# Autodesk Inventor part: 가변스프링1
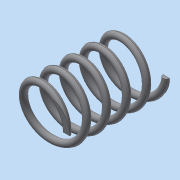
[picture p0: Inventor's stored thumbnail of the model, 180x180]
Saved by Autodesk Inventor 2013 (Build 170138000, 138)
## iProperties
Created: 2018-10
Part Number: 가변스프링1
Material: 일반
Document SubType Name: Modeling
Designer: Administrator
Density: 1 g/cm^3
Author: Administrator
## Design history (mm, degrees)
sketch "스케치1"
  geometry: L1 (0, 0)-(0, 30.256); L2 (0, 0)-(8, 0); L3 (0, 30.256)-(8, 30.256); C1 r 1 at (8, 0)
  constraints: 6 end point, 1 centre point, 1 coincident, 1 parallel, 1 perpendicular, 1 vertical
  dimensions: "d0" = 30.25555 distance of L1.start L1.end (derived); "d3" = 8 distance of L1.start L2.end; "d4" = 2 diameter of C1; "d5" = 8 distance of L1.end L3.end
feature "코일1" sketch "스케치1" pitch "d6" = 10; turns "d8" = 5; dims "d7" = 30.25555 (= d0), "d9" = 0, angle "d10" = 90 deg, angle "d11" = 90 deg, "d12" = 0, "d13" = 0
sketch "스케치2"
  geometry: L1 (30.256, 10)-(0, 10); L2 (0, 10)-(0, -10); L3 (0, -10)-(30.256, -10); L4 (30.256, -10)-(30.256, 10); 2 further points
  constraints: 8 end point, 2 parallel, 1 coincident, 1 horizontal, 1 midpoint, 1 perpendicular
  dimensions: "d14" = 30.25555 distance of L2.end L3.end (derived); "d16" = 20 distance of L3.end L1.start
extrude "돌출1" sketch "스케치2" stored distance "d17" = 0; taper "d18" = 0 deg
node "솔리드1"
